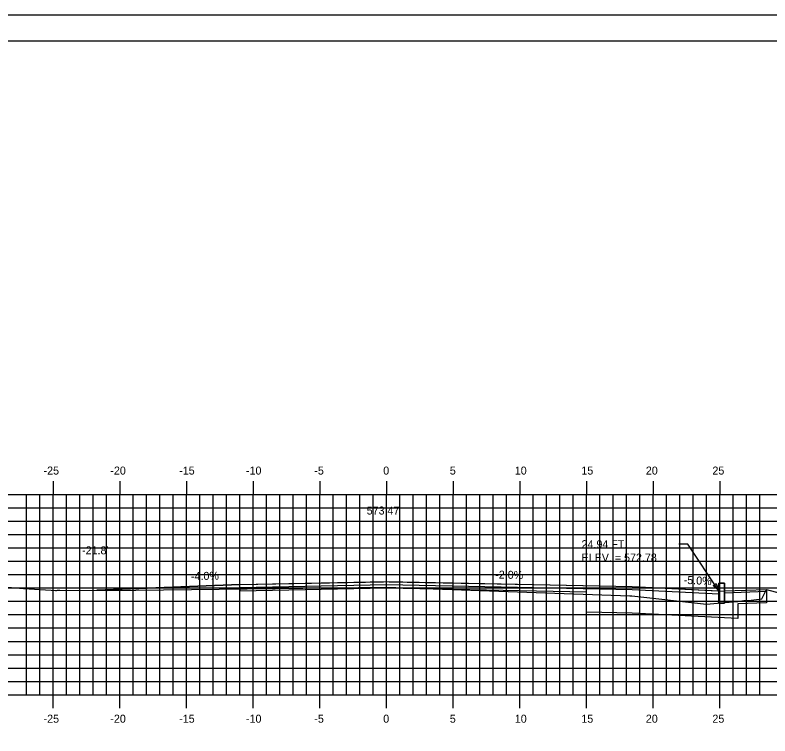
# Model space of a CAD drawing. Extents: x 1048109 to 1048279, y 781630 to 781740.
# Drawn here: x 1048163.9 to 1048220.5, y 781686.1 to 781740.1 of the extents above; entities that cross this region are included whole.
import ezdxf

# ---------------------------------------------------------------- set-up
doc = ezdxf.new("R2010")
doc.units = 0
for name, color, linetype in [('ANNOTATION', 7, 'Continuous'), ('D_Curb_Type1_Lt', 7, 'Continuous'), ('D_Drainage_Underdrain_06in', 7, 'Continuous'), ('D_Roadway_Centerline', 7, 'Continuous'), ('D_Roadway_Centerline_Text', 7, 'Continuous'), ('D_Roadway_Edge_Pavement', 7, 'Continuous'), ('D_Roadway_SlopeLines', 7, 'Continuous'), ('D_Roadway_SubGrade', 7, 'Continuous'), ('D_Text_Standard', 7, 'Continuous'), ('Default', 7, 'Continuous'), ('H_V ANNOTATION', 7, 'Continuous'), ('MAJOR', 7, 'Continuous'), ('MINOR', 7, 'Continuous'), ('S_Roadway_Centerline', 7, 'Continuous'), ('S_Roadway_Edge_Pavement', 7, 'Continuous')]:
    doc.layers.add(name, color=color, linetype=linetype)

msp = doc.modelspace()

# ---------------------------------------------------------------- linework, layer by layer
at = {"layer": 'ANNOTATION'}
msp.add_line((1048180.732, 781697.448), (1048170.004, 781697.019), dxfattribs=at)
at = {"layer": 'D_Curb_Type1_Lt'}
for points in [[(1048216.669, 781697.558), (1048216.669, 781696.058), (1048217.086, 781696.058), (1048217.086, 781697.558)], [(1048217.086, 781697.558), (1048217.086, 781696.058), (1048216.669, 781696.058), (1048216.669, 781697.558)]]:
    msp.add_lwpolyline(points, close=True, dxfattribs=at)
at = {"layer": 'D_Drainage_Underdrain_06in'}
msp.add_line((1048191.733, 781697.669), (1048210.158, 781697.3), dxfattribs=at)
at = {"layer": 'D_Roadway_Centerline'}
msp.add_line((1048206.733, 781695.369), (1048206.733, 781696.869), dxfattribs=at)
msp.add_lwpolyline([(1048170.004, 781697.019), (1048180.732, 781697.448), (1048191.503, 781697.664), (1048191.732, 781697.668), (1048191.927, 781697.664), (1048202.732, 781697.448), (1048210.158, 781697.3), (1048217.086, 781696.954)], dxfattribs=at)
at = {"layer": 'D_Roadway_Edge_Pavement'}
msp.add_lwpolyline([(1048216.669, 781696.724), (1048210.158, 781697.05), (1048191.733, 781697.419), (1048180.733, 781697.199), (1048180.733, 781697.449), (1048191.733, 781697.669), (1048210.158, 781697.3), (1048216.669, 781696.975)], dxfattribs=at)
at = {"layer": 'D_Roadway_SlopeLines'}
msp.add_line((1048210.158, 781697.3), (1048217.086, 781696.954), dxfattribs=at)
at = {"layer": 'D_Roadway_SubGrade'}
for p, q in [((1048180.733, 781697.199), (1048180.733, 781696.949)), ((1048220.247, 781696.091), (1048218.086, 781696.011)), ((1048218.086, 781696.011), (1048218.086, 781694.902))]:
    msp.add_line(p, q, dxfattribs=at)
for points in [[(1048206.733, 781696.869), (1048191.733, 781697.169), (1048180.741, 781696.949), (1048180.733, 781696.949)], [(1048217.086, 781696.975), (1048220.247, 781697.091), (1048220.247, 781696.924), (1048217.086, 781696.808)], [(1048220.247, 781697.091), (1048220.247, 781696.091)], [(1048218.086, 781694.902), (1048210.158, 781695.3), (1048206.733, 781695.369), (1048206.733, 781695.369), (1048206.731, 781695.987), (1048206.732, 781696.29)]]:
    msp.add_lwpolyline(points, dxfattribs=at)
at = {"layer": 'D_Text_Standard'}
msp.add_lwpolyline([(1048216.669, 781696.975), (1048214.333, 781700.475), (1048213.653, 781700.475)], dxfattribs=at)
msp.add_lwpolyline([(1048216.669, 781696.975), (1048216.225, 781697.378), (1048216.467, 781697.54)], close=True, dxfattribs=at)
at = {"layer": 'Default'}
msp.add_line((1048276.734, 781738.195), (1048116.734, 781738.195), dxfattribs=at)
msp.add_lwpolyline([(1048108.64, 781630.136), (1048278.64, 781630.136), (1048278.64, 781740.136), (1048108.64, 781740.136)], close=True, dxfattribs=at)
at = {"layer": 'MAJOR'}
for p, q in [((1048166.733, 781705.197), (1048166.733, 781704.195)), ((1048166.733, 781705.197), (1048166.733, 781704.195)), ((1048171.733, 781705.197), (1048171.733, 781704.195)), ((1048171.733, 781705.197), (1048171.733, 781704.195)), ((1048176.733, 781705.197), (1048176.733, 781704.195)), ((1048176.733, 781705.197), (1048176.733, 781704.195)), ((1048181.733, 781705.197), (1048181.733, 781704.195)), ((1048181.733, 781705.197), (1048181.733, 781704.195)), ((1048186.733, 781705.197), (1048186.733, 781704.195)), ((1048186.733, 781705.197), (1048186.733, 781704.195)), ((1048191.733, 781705.197), (1048191.733, 781704.195)), ((1048191.733, 781705.197), (1048191.733, 781704.195)), ((1048196.733, 781705.197), (1048196.733, 781704.195)), ((1048196.733, 781705.197), (1048196.733, 781704.195)), ((1048201.733, 781705.197), (1048201.733, 781704.195)), ((1048201.733, 781705.197), (1048201.733, 781704.195)), ((1048206.733, 781705.197), (1048206.733, 781704.195)), ((1048206.733, 781705.197), (1048206.733, 781704.195)), ((1048211.733, 781705.197), (1048211.733, 781704.195)), ((1048211.733, 781705.197), (1048211.733, 781704.195)), ((1048216.733, 781705.197), (1048216.733, 781704.195)), ((1048216.733, 781705.197), (1048216.733, 781704.195)), ((1048121.733, 781704.195), (1048261.733, 781704.195)), ((1048121.733, 781704.195), (1048261.733, 781704.195)), ((1048121.733, 781704.195), (1048261.733, 781704.195)), ((1048121.733, 781704.195), (1048261.733, 781704.195)), ((1048166.733, 781689.195), (1048166.733, 781704.195)), ((1048166.733, 781689.195), (1048166.733, 781704.195)), ((1048171.733, 781689.195), (1048171.733, 781704.195)), ((1048171.733, 781689.195), (1048171.733, 781704.195)), ((1048176.733, 781689.195), (1048176.733, 781704.195)), ((1048176.733, 781689.195), (1048176.733, 781704.195)), ((1048181.733, 781689.195), (1048181.733, 781704.195)), ((1048181.733, 781689.195), (1048181.733, 781704.195)), ((1048186.733, 781689.195), (1048186.733, 781704.195)), ((1048186.733, 781689.195), (1048186.733, 781704.195)), ((1048191.733, 781689.195), (1048191.733, 781704.195)), ((1048191.733, 781689.195), (1048191.733, 781704.195)), ((1048196.733, 781689.195), (1048196.733, 781704.195)), ((1048196.733, 781689.195), (1048196.733, 781704.195)), ((1048201.733, 781689.195), (1048201.733, 781704.195)), ((1048201.733, 781689.195), (1048201.733, 781704.195)), ((1048206.733, 781689.195), (1048206.733, 781704.195)), ((1048206.733, 781689.195), (1048206.733, 781704.195)), ((1048211.733, 781689.195), (1048211.733, 781704.195)), ((1048211.733, 781689.195), (1048211.733, 781704.195)), ((1048216.733, 781689.195), (1048216.733, 781704.195)), ((1048216.733, 781689.195), (1048216.733, 781704.195)), ((1048121.733, 781699.195), (1048261.733, 781699.195)), ((1048121.733, 781699.195), (1048261.733, 781699.195)), ((1048121.733, 781694.195), (1048261.733, 781694.195)), ((1048121.733, 781694.195), (1048261.733, 781694.195)), ((1048121.733, 781689.195), (1048261.733, 781689.195)), ((1048121.733, 781689.195), (1048261.733, 781689.195)), ((1048121.733, 781689.195), (1048261.733, 781689.195)), ((1048121.733, 781689.195), (1048261.733, 781689.195)), ((1048166.733, 781688.193), (1048166.733, 781689.195)), ((1048166.733, 781688.193), (1048166.733, 781689.195)), ((1048171.733, 781688.193), (1048171.733, 781689.195)), ((1048171.733, 781688.193), (1048171.733, 781689.195)), ((1048176.733, 781688.193), (1048176.733, 781689.195)), ((1048176.733, 781688.193), (1048176.733, 781689.195)), ((1048181.733, 781688.193), (1048181.733, 781689.195)), ((1048181.733, 781688.193), (1048181.733, 781689.195)), ((1048186.733, 781688.193), (1048186.733, 781689.195)), ((1048186.733, 781688.193), (1048186.733, 781689.195)), ((1048191.733, 781688.193), (1048191.733, 781689.195)), ((1048191.733, 781688.193), (1048191.733, 781689.195)), ((1048196.733, 781688.193), (1048196.733, 781689.195)), ((1048196.733, 781688.193), (1048196.733, 781689.195)), ((1048201.733, 781688.193), (1048201.733, 781689.195)), ((1048201.733, 781688.193), (1048201.733, 781689.195)), ((1048206.733, 781688.193), (1048206.733, 781689.195)), ((1048206.733, 781688.193), (1048206.733, 781689.195)), ((1048211.733, 781688.193), (1048211.733, 781689.195)), ((1048211.733, 781688.193), (1048211.733, 781689.195)), ((1048216.733, 781688.193), (1048216.733, 781689.195)), ((1048216.733, 781688.193), (1048216.733, 781689.195))]:
    msp.add_line(p, q, dxfattribs=at)
at = {"layer": 'MINOR'}
for p, q in [((1048164.733, 781689.195), (1048164.733, 781704.195)), ((1048164.733, 781689.195), (1048164.733, 781704.195)), ((1048165.733, 781689.195), (1048165.733, 781704.195)), ((1048165.733, 781689.195), (1048165.733, 781704.195)), ((1048167.733, 781689.195), (1048167.733, 781704.195)), ((1048167.733, 781689.195), (1048167.733, 781704.195)), ((1048168.733, 781689.195), (1048168.733, 781704.195)), ((1048168.733, 781689.195), (1048168.733, 781704.195)), ((1048169.733, 781689.195), (1048169.733, 781704.195)), ((1048169.733, 781689.195), (1048169.733, 781704.195)), ((1048170.733, 781689.195), (1048170.733, 781704.195)), ((1048170.733, 781689.195), (1048170.733, 781704.195)), ((1048172.733, 781689.195), (1048172.733, 781704.195)), ((1048172.733, 781689.195), (1048172.733, 781704.195)), ((1048173.733, 781689.195), (1048173.733, 781704.195)), ((1048173.733, 781689.195), (1048173.733, 781704.195)), ((1048174.733, 781689.195), (1048174.733, 781704.195)), ((1048174.733, 781689.195), (1048174.733, 781704.195)), ((1048175.733, 781689.195), (1048175.733, 781704.195)), ((1048175.733, 781689.195), (1048175.733, 781704.195)), ((1048177.733, 781689.195), (1048177.733, 781704.195)), ((1048177.733, 781689.195), (1048177.733, 781704.195)), ((1048178.733, 781689.195), (1048178.733, 781704.195)), ((1048178.733, 781689.195), (1048178.733, 781704.195)), ((1048179.733, 781689.195), (1048179.733, 781704.195)), ((1048179.733, 781689.195), (1048179.733, 781704.195)), ((1048180.733, 781689.195), (1048180.733, 781704.195)), ((1048180.733, 781689.195), (1048180.733, 781704.195)), ((1048182.733, 781689.195), (1048182.733, 781704.195)), ((1048182.733, 781689.195), (1048182.733, 781704.195)), ((1048183.733, 781689.195), (1048183.733, 781704.195)), ((1048183.733, 781689.195), (1048183.733, 781704.195)), ((1048184.733, 781689.195), (1048184.733, 781704.195)), ((1048184.733, 781689.195), (1048184.733, 781704.195)), ((1048185.733, 781689.195), (1048185.733, 781704.195)), ((1048185.733, 781689.195), (1048185.733, 781704.195)), ((1048187.733, 781689.195), (1048187.733, 781704.195)), ((1048187.733, 781689.195), (1048187.733, 781704.195)), ((1048188.733, 781689.195), (1048188.733, 781704.195)), ((1048188.733, 781689.195), (1048188.733, 781704.195)), ((1048189.733, 781689.195), (1048189.733, 781704.195)), ((1048189.733, 781689.195), (1048189.733, 781704.195)), ((1048190.733, 781689.195), (1048190.733, 781704.195)), ((1048190.733, 781689.195), (1048190.733, 781704.195)), ((1048192.733, 781689.195), (1048192.733, 781704.195)), ((1048192.733, 781689.195), (1048192.733, 781704.195)), ((1048193.733, 781689.195), (1048193.733, 781704.195)), ((1048193.733, 781689.195), (1048193.733, 781704.195)), ((1048194.733, 781689.195), (1048194.733, 781704.195)), ((1048194.733, 781689.195), (1048194.733, 781704.195)), ((1048195.733, 781689.195), (1048195.733, 781704.195)), ((1048195.733, 781689.195), (1048195.733, 781704.195)), ((1048197.733, 781689.195), (1048197.733, 781704.195)), ((1048197.733, 781689.195), (1048197.733, 781704.195)), ((1048198.733, 781689.195), (1048198.733, 781704.195)), ((1048198.733, 781689.195), (1048198.733, 781704.195)), ((1048199.733, 781689.195), (1048199.733, 781704.195)), ((1048199.733, 781689.195), (1048199.733, 781704.195)), ((1048200.733, 781689.195), (1048200.733, 781704.195)), ((1048200.733, 781689.195), (1048200.733, 781704.195)), ((1048202.733, 781689.195), (1048202.733, 781704.195)), ((1048202.733, 781689.195), (1048202.733, 781704.195)), ((1048203.733, 781689.195), (1048203.733, 781704.195)), ((1048203.733, 781689.195), (1048203.733, 781704.195)), ((1048204.733, 781689.195), (1048204.733, 781704.195)), ((1048204.733, 781689.195), (1048204.733, 781704.195)), ((1048205.733, 781689.195), (1048205.733, 781704.195)), ((1048205.733, 781689.195), (1048205.733, 781704.195)), ((1048207.733, 781689.195), (1048207.733, 781704.195)), ((1048207.733, 781689.195), (1048207.733, 781704.195)), ((1048208.733, 781689.195), (1048208.733, 781704.195)), ((1048208.733, 781689.195), (1048208.733, 781704.195)), ((1048209.733, 781689.195), (1048209.733, 781704.195)), ((1048209.733, 781689.195), (1048209.733, 781704.195)), ((1048210.733, 781689.195), (1048210.733, 781704.195)), ((1048210.733, 781689.195), (1048210.733, 781704.195)), ((1048212.733, 781689.195), (1048212.733, 781704.195)), ((1048212.733, 781689.195), (1048212.733, 781704.195)), ((1048213.733, 781689.195), (1048213.733, 781704.195)), ((1048213.733, 781689.195), (1048213.733, 781704.195)), ((1048214.733, 781689.195), (1048214.733, 781704.195)), ((1048214.733, 781689.195), (1048214.733, 781704.195)), ((1048215.733, 781689.195), (1048215.733, 781704.195)), ((1048215.733, 781689.195), (1048215.733, 781704.195)), ((1048217.733, 781689.195), (1048217.733, 781704.195)), ((1048217.733, 781689.195), (1048217.733, 781704.195)), ((1048218.733, 781689.195), (1048218.733, 781704.195)), ((1048218.733, 781689.195), (1048218.733, 781704.195)), ((1048219.733, 781689.195), (1048219.733, 781704.195)), ((1048219.733, 781689.195), (1048219.733, 781704.195)), ((1048121.733, 781703.195), (1048261.733, 781703.195)), ((1048121.733, 781703.195), (1048261.733, 781703.195)), ((1048121.733, 781702.195), (1048261.733, 781702.195)), ((1048121.733, 781702.195), (1048261.733, 781702.195)), ((1048121.733, 781701.195), (1048261.733, 781701.195)), ((1048121.733, 781701.195), (1048261.733, 781701.195)), ((1048121.733, 781700.195), (1048261.733, 781700.195)), ((1048121.733, 781700.195), (1048261.733, 781700.195)), ((1048121.733, 781698.195), (1048261.733, 781698.195)), ((1048121.733, 781698.195), (1048261.733, 781698.195)), ((1048121.733, 781697.195), (1048261.733, 781697.195)), ((1048121.733, 781697.195), (1048187.041, 781697.195)), ((1048121.733, 781696.195), (1048261.733, 781696.195)), ((1048121.733, 781696.195), (1048261.733, 781696.195)), ((1048121.733, 781695.195), (1048261.733, 781695.195)), ((1048121.733, 781695.195), (1048261.733, 781695.195)), ((1048121.733, 781693.195), (1048261.733, 781693.195)), ((1048121.733, 781693.195), (1048261.733, 781693.195)), ((1048121.733, 781692.195), (1048261.733, 781692.195)), ((1048121.733, 781692.195), (1048261.733, 781692.195)), ((1048121.733, 781691.195), (1048261.733, 781691.195)), ((1048121.733, 781691.195), (1048261.733, 781691.195)), ((1048121.733, 781690.195), (1048261.733, 781690.195)), ((1048121.733, 781690.195), (1048261.733, 781690.195))]:
    msp.add_line(p, q, dxfattribs=at)
at = {"layer": 'S_Roadway_Centerline'}
for points in [[(1048160.931, 781697.459), (1048164.515, 781697.164), (1048166.579, 781697.026), (1048166.904, 781697.016), (1048166.979, 781697.016), (1048167.062, 781697.019), (1048167.228, 781697.032), (1048170.85, 781697.015), (1048191.728, 781697.248), (1048209.98, 781696.6), (1048210.103, 781696.597), (1048210.142, 781696.595), (1048215.732, 781695.984), (1048217.111, 781696.111), (1048218.082, 781696.182), (1048218.534, 781696.259), (1048218.88, 781696.249), (1048219.893, 781696.369), (1048220.247, 781697.091), (1048222.193, 781696.555)], [(1048191.728, 781697.248), (1048191.728, 781697.248)]]:
    msp.add_lwpolyline(points, dxfattribs=at)
at = {"layer": 'S_Roadway_Edge_Pavement'}
for points in [[(1048167.229, 781697.032), (1048167.228, 781697.032)], [(1048218.534, 781696.259), (1048218.534, 781696.259)]]:
    msp.add_lwpolyline(points, dxfattribs=at)

# ---------------------------------------------------------------- texts
at = {"layer": 'ANNOTATION'}
for s, rotation, p in [("-21.8'", 360, (1048168.905, 781699.719)), ('-4.0%', 1.1455, (1048177.078, 781697.776)), ('-2.0%', 358.8567, (1048199.886, 781697.905)), ('-5.0%', 357.1376, (1048214.017, 781697.509))]:
    msp.add_text(s, height=0.6, rotation=rotation, dxfattribs=at).set_placement(p)
at = {"layer": 'D_Roadway_Centerline_Text'}
msp.add_text('573.47', height=0.6, dxfattribs=at).set_placement((1048190.251, 781702.7))
at = {"layer": 'D_Text_Standard'}
for s, p in [('24.94 FT.', (1048206.365, 781700.175)), ('ELEV. = 572.78', (1048206.365, 781699.175))]:
    msp.add_text(s, height=0.6, dxfattribs=at).set_placement(p)
at = {"layer": 'H_V ANNOTATION'}
for s, p in [('-25', (1048166.019, 781705.695)), ('-20', (1048171.027, 781705.695)), ('-15', (1048176.19, 781705.695)), ('-10', (1048181.198, 781705.695)), ('-5', (1048186.324, 781705.695)), ('0', (1048191.492, 781705.695)), ('5', (1048196.484, 781705.695)), ('10', (1048201.359, 781705.695)), ('15', (1048206.351, 781705.695)), ('20', (1048211.187, 781705.695)), ('25', (1048216.179, 781705.695)), ('-25', (1048166.019, 781687.095)), ('-20', (1048171.027, 781687.095)), ('-15', (1048176.19, 781687.095)), ('-10', (1048181.198, 781687.095)), ('-5', (1048186.324, 781687.095)), ('0', (1048191.492, 781687.095)), ('5', (1048196.484, 781687.095)), ('10', (1048201.359, 781687.095)), ('15', (1048206.351, 781687.095)), ('20', (1048211.187, 781687.095)), ('25', (1048216.179, 781687.095))]:
    msp.add_text(s, height=0.6, dxfattribs=at).set_placement(p)
at = {"layer": 'S_Roadway_Centerline'}
for s, p in [('L', (1048191.72, 781697.24)), ('C', (1048191.723, 781697.248))]:
    msp.add_text(s, height=0.0146, dxfattribs=at).set_placement(p)

doc.saveas('drawing.dxf')
